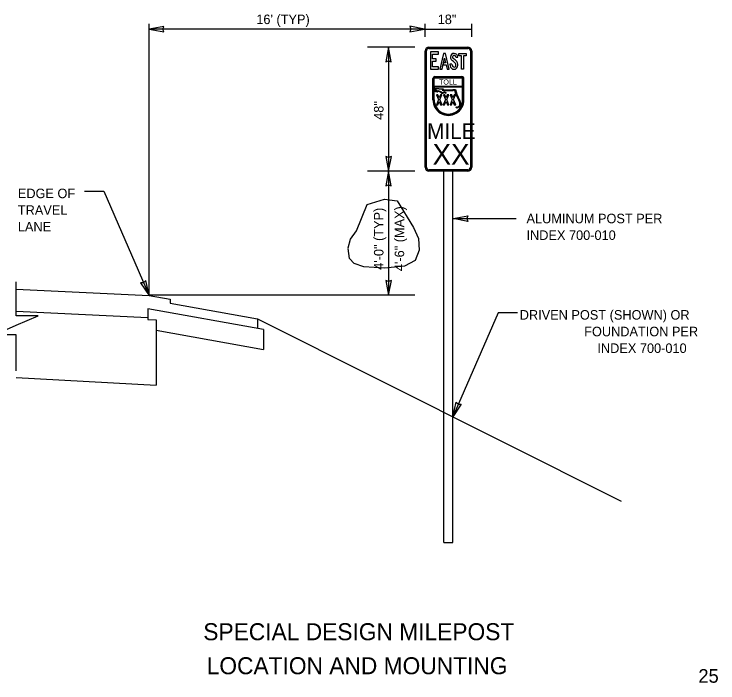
# Model space of a CAD drawing. Extents: x 56768 to 57406, y 11696 to 12105.
# Drawn here: x 57187.3 to 57394.2, y 11706.5 to 11903.1 of the extents above; entities that cross this region are included whole.
import ezdxf

# ---------------------------------------------------------------- set-up
doc = ezdxf.new("R2010")
doc.units = 0
for name, color, linetype in [('1', 7, 'Continuous'), ('52', 7, 'Continuous'), ('62', 7, 'Continuous'), ('Default', 7, 'Continuous'), ('DimLines_dp', 7, 'Continuous'), ('SignPanel', 7, 'Continuous'), ('TextMisc', 7, 'Continuous'), ('TextShtNo', 7, 'Continuous'), ('XSGrdLine_ex', 7, 'Continuous')]:
    doc.layers.add(name, color=color, linetype=linetype)

msp = doc.modelspace()

# ---------------------------------------------------------------- linework, layer by layer
at = {"layer": '1'}
for p, q in [((57313.6, 11786.05), (57313.6, 11856.93)), ((57316.26, 11784.71), (57316.26, 11856.93)), ((57313.6, 11747.72), (57313.6, 11786.05)), ((57316.26, 11747.72), (57316.26, 11784.71)), ((57313.6, 11747.72), (57316.26, 11747.72))]:
    msp.add_line(p, q, dxfattribs=at)
at = {"layer": '52'}
msp.add_line((57305.09, 11820.43), (57226.97, 11820.43), dxfattribs=at)
at = {"layer": '62'}
msp.add_lwpolyline([(57285.44, 11834.37), (57286.14, 11836.97), (57287.94, 11839.37), (57291.04, 11847.13), (57296.14, 11848.73), (57299.84, 11848.23), (57304.65, 11840.37), (57306.15, 11837.17), (57306.35, 11833.67), (57305.15, 11830.66), (57302.05, 11828.96), (57296.14, 11828.46), (57290.04, 11828.76), (57287.24, 11829.76), (57285.84, 11831.26), (57285.44, 11834.17)], dxfattribs=at)
at = {"layer": 'Default'}
msp.add_lwpolyline([(57187.88, 11798.24), (57187.88, 11808.8), (57181.42, 11808.8), (57187.88, 11811.61), (57194.34, 11814.43), (57187.88, 11814.43), (57187.88, 11824.43)], dxfattribs=at)
at = {"layer": 'DimLines_dp'}
for p, q in [((57226.97, 11820.43), (57226.97, 11900.25)), ((57231.32, 11899.52), (57226.97, 11898.71)), ((57230.99, 11898.71), (57231.32, 11899.52)), ((57307.91, 11898.71), (57303.56, 11899.55)), ((57303.56, 11899.55), (57303.89, 11898.71)), ((57308.09, 11896.42), (57308.09, 11900.25)), ((57321.78, 11896.42), (57321.78, 11900.25)), ((57308.09, 11898.71), (57226.97, 11898.71)), ((57226.97, 11898.71), (57231.32, 11897.87)), ((57231.32, 11897.87), (57230.99, 11898.71)), ((57303.89, 11898.71), (57303.56, 11897.9)), ((57303.56, 11897.9), (57307.91, 11898.71)), ((57308.09, 11898.71), (57321.78, 11898.71)), ((57305.09, 11893.42), (57291.17, 11893.42)), ((57297.35, 11893.42), (57296.51, 11889.07)), ((57297.35, 11893.42), (57297.35, 11856.93)), ((57298.16, 11889.07), (57297.35, 11893.42)), ((57296.51, 11889.07), (57297.35, 11889.4)), ((57297.35, 11889.4), (57298.16, 11889.07)), ((57297.35, 11860.95), (57296.54, 11861.28)), ((57296.54, 11861.28), (57297.35, 11856.93)), ((57297.35, 11860.95), (57296.54, 11861.28)), ((57296.54, 11861.28), (57297.35, 11856.93)), ((57297.35, 11856.93), (57298.19, 11861.28)), ((57298.19, 11861.28), (57297.35, 11860.95)), ((57297.35, 11856.93), (57298.19, 11861.28)), ((57298.19, 11861.28), (57297.35, 11860.95)), ((57305.09, 11856.93), (57291.17, 11856.93)), ((57297.35, 11856.93), (57296.51, 11852.58)), ((57297.35, 11856.93), (57297.35, 11820.43)), ((57298.16, 11852.58), (57297.35, 11856.93)), ((57296.51, 11852.58), (57297.35, 11852.91)), ((57297.35, 11852.91), (57298.16, 11852.58)), ((57208.01, 11851.04), (57213.65, 11851.04)), ((57213.65, 11851.04), (57226.97, 11820.42)), ((57316.32, 11842.98), (57320.67, 11843.82)), ((57320.67, 11843.82), (57320.34, 11842.98)), ((57316.32, 11842.98), (57334.84, 11842.98)), ((57320.67, 11842.17), (57316.32, 11842.98)), ((57320.34, 11842.98), (57320.67, 11842.17)), ((57225.37, 11824.11), (57224.49, 11824.09)), ((57224.49, 11824.09), (57226.97, 11820.42)), ((57226.01, 11824.75), (57225.37, 11824.11)), ((57226.97, 11820.42), (57226.01, 11824.75)), ((57297.35, 11824.45), (57296.54, 11824.78)), ((57296.54, 11824.78), (57297.35, 11820.43)), ((57297.35, 11820.43), (57298.19, 11824.78)), ((57298.19, 11824.78), (57297.35, 11824.45)), ((57329.59, 11815.33), (57316.26, 11784.71)), ((57335.23, 11815.33), (57329.59, 11815.33)), ((57316.26, 11784.71), (57317.23, 11789.03)), ((57318.74, 11788.38), (57316.26, 11784.71)), ((57317.23, 11789.03), (57317.87, 11788.4)), ((57317.87, 11788.4), (57318.74, 11788.38))]:
    msp.add_line(p, q, dxfattribs=at)
at = {"layer": 'SignPanel'}
for p, q in [((57317.13, 11890.42), (57317.71, 11890.42)), ((57317.13, 11890.42), (57317.71, 11890.42)), ((57317.13, 11890.42), (57317.71, 11890.42)), ((57315.99, 11888.38), (57315.4, 11888.38)), ((57315.99, 11888.38), (57315.4, 11888.38)), ((57315.99, 11888.38), (57315.4, 11888.38)), ((57310.37, 11877.91), (57310.37, 11884.19)), ((57310.57, 11877.91), (57310.57, 11884.19)), ((57310.75, 11881.91), (57310.75, 11884.19)), ((57310.94, 11884.76), (57318.93, 11884.76)), ((57310.94, 11884.56), (57318.93, 11884.56)), ((57310.94, 11884.37), (57318.93, 11884.37)), ((57319.12, 11881.91), (57319.12, 11884.19)), ((57319.31, 11877.91), (57319.31, 11884.19)), ((57319.5, 11877.91), (57319.5, 11884.19)), ((57310.75, 11881.91), (57319.12, 11881.91)), ((57310.75, 11877.91), (57310.75, 11881.71)), ((57310.75, 11881.71), (57319.12, 11881.71)), ((57311.14, 11880.26), (57310.97, 11881.35)), ((57310.97, 11881.35), (57313.35, 11881.16)), ((57313.19, 11880.95), (57311.24, 11881.1)), ((57311.24, 11881.1), (57311.34, 11880.46)), ((57312.23, 11881.01), (57312.23, 11881.01)), ((57313.32, 11880.59), (57313.19, 11880.95)), ((57313.35, 11881.16), (57313.48, 11880.82)), ((57313.48, 11880.82), (57316.21, 11880.82)), ((57316.21, 11880.82), (57316.31, 11880.97)), ((57316.31, 11880.97), (57317.05, 11880.97)), ((57317.05, 11880.97), (57317.38, 11879.54)), ((57319.12, 11877.91), (57319.12, 11881.71)), ((57311.59, 11880.2), (57311.14, 11880.26)), ((57311.34, 11880.46), (57311.53, 11880.44)), ((57311.53, 11880.44), (57311.8, 11880.65)), ((57311.84, 11880.4), (57311.59, 11880.2)), ((57311.8, 11880.65), (57312.71, 11880.36)), ((57312.6, 11880.15), (57311.84, 11880.4)), ((57313.13, 11879.65), (57312.6, 11880.15)), ((57312.71, 11880.36), (57313.17, 11879.94)), ((57313.77, 11880.03), (57313.13, 11879.65)), ((57313.17, 11879.94), (57313.78, 11880.3)), ((57316.33, 11880.59), (57313.32, 11880.59)), ((57314.15, 11879.77), (57313.77, 11880.03)), ((57313.78, 11880.3), (57314.27, 11879.96)), ((57314.27, 11879.96), (57314.15, 11879.77)), ((57316.44, 11880.74), (57316.33, 11880.59)), ((57316.87, 11880.74), (57316.44, 11880.74)), ((57317.17, 11879.45), (57316.87, 11880.74)), ((57317.6, 11878.75), (57317.17, 11879.45)), ((57317.38, 11879.54), (57317.83, 11878.81)), ((57317.6, 11878.57), (57317.6, 11878.75)), ((57317.83, 11878.81), (57317.83, 11878.63)), ((57318.03, 11877.86), (57317.6, 11878.57)), ((57317.83, 11878.63), (57318.24, 11877.96)), ((57318.27, 11877), (57318.03, 11877.86)), ((57318.24, 11877.96), (57318.5, 11877.03)), ((57318.27, 11876.28), (57318.27, 11877)), ((57318.5, 11877.03), (57318.5, 11876.17)), ((57317.16, 11875.63), (57317.29, 11875.82)), ((57317.39, 11875.47), (57317.16, 11875.63)), ((57317.29, 11875.82), (57317.43, 11875.72)), ((57317.74, 11875.56), (57317.39, 11875.47)), ((57317.43, 11875.72), (57317.64, 11875.77)), ((57317.64, 11875.77), (57318.27, 11876.28)), ((57318.5, 11876.17), (57317.74, 11875.56))]:
    msp.add_line(p, q, dxfattribs=at)
for points in [[(57309.23, 11893.42), (57320.64, 11893.42)], [(57308.09, 11858.07), (57308.09, 11892.28)], [(57308.47, 11858.07), (57308.47, 11892.28)], [(57309.23, 11893.04), (57320.64, 11893.04)], [(57321.4, 11892.28), (57321.4, 11858.07)], [(57321.78, 11892.28), (57321.78, 11858.07)], [(57320.64, 11857.31), (57309.23, 11857.31)], [(57320.64, 11856.93), (57309.23, 11856.93)]]:
    msp.add_lwpolyline(points, dxfattribs=at)
for points in [[(57310.29, 11887.65), (57310.29, 11889.27), (57311.31, 11889.27), (57311.31, 11889.98), (57310.29, 11889.98), (57310.29, 11891.3), (57312.02, 11891.3), (57312.02, 11892), (57309.64, 11892), (57309.64, 11886.94), (57312.02, 11886.94), (57312.02, 11887.65)], [(57310.29, 11887.65), (57310.29, 11889.27), (57311.31, 11889.27), (57311.31, 11889.98), (57310.29, 11889.98), (57310.29, 11891.3), (57312.02, 11891.3), (57312.02, 11892), (57309.64, 11892), (57309.64, 11886.94), (57312.02, 11886.94), (57312.02, 11887.65)], [(57310.29, 11887.65), (57310.29, 11889.27), (57311.31, 11889.27), (57311.31, 11889.98), (57310.29, 11889.98), (57310.29, 11891.3), (57312.02, 11891.3), (57312.02, 11892), (57309.64, 11892), (57309.64, 11886.94), (57312.02, 11886.94), (57312.02, 11887.65)], [(57314.26, 11888.17), (57314.54, 11886.94), (57315.14, 11886.94), (57314.12, 11891.52), (57313.49, 11891.52), (57312.47, 11886.94), (57313.08, 11886.94), (57313.35, 11888.17)], [(57313.49, 11888.81), (57313.35, 11888.17), (57314.26, 11888.17), (57314.54, 11886.94), (57315.14, 11886.94), (57314.12, 11891.52), (57313.49, 11891.52), (57312.47, 11886.94), (57313.08, 11886.94), (57313.81, 11890.21), (57314.12, 11888.81)], [(57313.49, 11888.81), (57313.35, 11888.17), (57314.26, 11888.17), (57314.54, 11886.94), (57315.14, 11886.94), (57314.12, 11891.52), (57313.49, 11891.52), (57312.47, 11886.94), (57313.08, 11886.94), (57313.81, 11890.21), (57314.12, 11888.81)], [(57318.77, 11890.88), (57318, 11890.88), (57318, 11891.52), (57320.14, 11891.52), (57320.14, 11890.88), (57319.36, 11890.88), (57319.36, 11886.94), (57318.77, 11886.94)], [(57318.77, 11890.88), (57318, 11890.88), (57318, 11891.52), (57320.14, 11891.52), (57320.14, 11890.88), (57319.36, 11890.88), (57319.36, 11886.94), (57318.77, 11886.94)], [(57318.77, 11890.88), (57318, 11890.88), (57318, 11891.52), (57320.14, 11891.52), (57320.14, 11890.88), (57319.36, 11890.88), (57319.36, 11886.94), (57318.77, 11886.94)], [(57313.81, 11890.21), (57314.12, 11888.81), (57313.49, 11888.81)], [(57311.83, 11876.49), (57312.23, 11877.47), (57312.64, 11876.49), (57313.07, 11876.49), (57312.45, 11877.98), (57313.02, 11879.34), (57312.59, 11879.34), (57312.23, 11878.49), (57311.88, 11879.34), (57311.45, 11879.34), (57312.02, 11877.98), (57311.4, 11876.49)], [(57313.84, 11876.49), (57314.25, 11877.47), (57314.66, 11876.49), (57315.08, 11876.49), (57314.46, 11877.98), (57315.03, 11879.34), (57314.61, 11879.34), (57314.25, 11878.49), (57313.89, 11879.34), (57313.46, 11879.34), (57314.04, 11877.98), (57313.41, 11876.49)], [(57315.86, 11876.49), (57316.27, 11877.47), (57316.67, 11876.49), (57317.1, 11876.49), (57316.48, 11877.98), (57317.05, 11879.34), (57316.62, 11879.34), (57316.27, 11878.49), (57315.91, 11879.34), (57315.48, 11879.34), (57316.05, 11877.98), (57315.43, 11876.49)]]:
    msp.add_lwpolyline(points, close=True, dxfattribs=at)
for centre, radius, start, end in [((57309.23, 11892.28), 1.14, 90, 180), ((57320.64, 11892.28), 1.14, 0, 90), ((57309.23, 11892.28), 0.76, 90, 180), ((57320.64, 11892.28), 0.76, 0, 90), ((57309.23, 11858.07), 1.14, 180, 270), ((57309.23, 11858.07), 0.76, 180, 270), ((57320.64, 11858.07), 1.14, 270, 360), ((57320.64, 11858.07), 0.76, 270, 360)]:
    msp.add_arc(centre, radius, start, end, dxfattribs=at)
for centre, major_axis, ratio, start_param, end_param in [((57316.62, 11890.39), (0, 1.19), 0.91923, 4.736267, 7.790596), ((57316.62, 11890.39), (0, 1.19), 0.91923, 4.736267, 7.790596), ((57316.62, 11890.39), (0, 1.19), 0.91923, 4.736267, 7.790596), ((57316.51, 11890.42), (0, 1.07), 0.91923, 1.534831, 2.511766), ((57316.51, 11890.42), (0, 1.07), 0.91923, 1.534831, 2.511766), ((57316.51, 11890.42), (0, 1.07), 0.91923, 1.534831, 2.511766), ((57313.91, 11885.49), (0, 4.63), 0.91923, 5.515137, 5.786988), ((57313.91, 11885.49), (0, 4.63), 0.91923, 5.515137, 5.786988), ((57313.91, 11885.49), (0, 4.63), 0.91923, 5.515137, 5.786988), ((57316.55, 11890.44), (0, 0.46), 0.91923, 0.87378, 2.656959), ((57316.55, 11890.44), (0, 0.46), 0.91923, 0.87378, 2.656959), ((57316.55, 11890.44), (0, 0.46), 0.91923, 0.87378, 2.656959), ((57316.62, 11890.37), (0, 0.558), 0.91923, 4.786904, 7.140738), ((57316.62, 11890.37), (0, 0.558), 0.91923, 4.786904, 7.140738), ((57316.62, 11890.37), (0, 0.558), 0.91923, 4.786904, 7.140738), ((57314.42, 11886.19), (0, 4.39), 0.91923, 5.462886, 5.782242), ((57314.42, 11886.19), (0, 4.39), 0.91923, 5.462886, 5.782242), ((57314.42, 11886.19), (0, 4.39), 0.91923, 5.462886, 5.782242), ((57316.44, 11888.19), (0, 1.42), 0.91923, 4.260987, 5.485755), ((57316.44, 11888.19), (0, 1.42), 0.91923, 4.260987, 5.485755), ((57316.44, 11888.19), (0, 1.42), 0.91923, 4.260987, 5.485755), ((57316.77, 11888.31), (0, 1.5), 0.91923, 1.526364, 2.701682), ((57316.77, 11888.31), (0, 1.5), 0.91923, 1.526364, 2.701682), ((57316.77, 11888.31), (0, 1.5), 0.91923, 1.526364, 2.701682), ((57316.83, 11888.33), (0, 0.911), 0.91923, 1.524757, 2.28214), ((57316.83, 11888.33), (0, 0.911), 0.91923, 1.524757, 2.28214), ((57316.83, 11888.33), (0, 0.911), 0.91923, 1.524757, 2.28214), ((57316.61, 11888.11), (0, 0.581), 0.91923, 2.261787, 4.23006), ((57316.61, 11888.11), (0, 0.581), 0.91923, 2.261787, 4.23006), ((57316.61, 11888.11), (0, 0.581), 0.91923, 2.261787, 4.23006), ((57316.58, 11888.12), (0, 1.24), 0.91923, 2.786047, 4.251692), ((57316.58, 11888.12), (0, 1.24), 0.91923, 2.786047, 4.251692), ((57316.58, 11888.12), (0, 1.24), 0.91923, 2.786047, 4.251692), ((57316.43, 11888.19), (0, 0.792), 0.91923, 4.254409, 5.632398), ((57316.43, 11888.19), (0, 0.792), 0.91923, 4.254409, 5.632398), ((57316.43, 11888.19), (0, 0.792), 0.91923, 4.254409, 5.632398), ((57310.95, 11884.18), (0, 0.57), 0.9997, 0, 1.570796), ((57310.95, 11884.18), (0, 0.38), 0.9997, 0, 1.570796), ((57310.95, 11884.18), (0, 0.19), 0.9997, 0, 1.570796), ((57318.93, 11884.18), (0, 0.57), 0.9997, 4.712389, 6.283185), ((57318.93, 11884.18), (0, 0.38), 0.9997, 4.712389, 6.283185), ((57318.93, 11884.18), (0, 0.19), 0.9997, 4.712389, 6.283185), ((57314.94, 11877.91), (0, -4.56), 0.9997, 4.712389, 7.853982), ((57314.94, 11877.91), (0, -4.37), 0.9997, 4.712389, 7.853982), ((57314.94, 11877.91), (0, -4.18), 0.9997, 4.712389, 7.853982)]:
    msp.add_ellipse(centre, major_axis=major_axis, ratio=ratio, start_param=start_param, end_param=end_param, dxfattribs=at)
at = {"layer": 'XSGrdLine_ex'}
for p, q in [((57226.97, 11820.42), (57233.13, 11819.31)), ((57233.13, 11819.31), (57233.13, 11818.14)), ((57233.13, 11818.14), (57258.85, 11813.51)), ((57226.56, 11816.48), (57226.56, 11813.33)), ((57260.55, 11810.37), (57226.56, 11816.48)), ((57226.56, 11813.33), (57229.03, 11813.18)), ((57229.03, 11813.18), (57229.03, 11794)), ((57258.85, 11813.51), (57258.85, 11810.67)), ((57229.03, 11810.22), (57260.55, 11804.55)), ((57260.55, 11810.37), (57260.55, 11804.55)), ((57187.88, 11796.28), (57229.03, 11794))]:
    msp.add_line(p, q, dxfattribs=at)
for points in [[(57187.88, 11822.28), (57226.97, 11820.42)], [(57187.88, 11815.78), (57226.56, 11813.95)], [(57258.85, 11813.51), (57365.73, 11759.9)]]:
    msp.add_lwpolyline(points, dxfattribs=at)

# ---------------------------------------------------------------- texts
at = {"layer": 'DimLines_dp'}
for s, p in [("16' (TYP)", (57258.48, 11900.18)), ('18"', (57311.8, 11900.18)), ('EDGE OF ', (57188.39, 11849)), ('TRAVEL ', (57188.39, 11844.1)), ('ALUMINUM POST PER', (57337.9, 11841.62)), ('LANE', (57188.39, 11839.2)), ('INDEX 700-010', (57337.9, 11836.72)), ('DRIVEN POST (SHOWN) OR', (57335.91, 11813.29)), ('FOUNDATION PER', (57354.85, 11808.39)), ('INDEX 700-010', (57358.74, 11803.49))]:
    msp.add_text(s, height=2.8, dxfattribs=at).set_placement(p)
for s, p in [('48"', (57295.86, 11872.03)), ('4\'-0" (TYP)', (57295.86, 11827.92)), ('4\'-6" (MAX)', (57301.94, 11827.53))]:
    msp.add_text(s, height=2.8, rotation=90, dxfattribs=at).set_placement(p)
at = {"layer": 'SignPanel'}
for s, height, p in [('TOLL', 1.519, (57312.18, 11882.38)), ('MILE', 4.562, (57308.68, 11866.42)), ('XX', 6.083, (57310.29, 11858.86))]:
    msp.add_text(s, height=height, dxfattribs=at).set_placement(p)
at = {"layer": 'TextMisc'}
for s, p in [('SPECIAL DESIGN MILEPOST ', (57242.9, 11719.02)), (' LOCATION AND MOUNTING  ', (57242.04, 11709.02))]:
    msp.add_text(s, height=5, rotation=360, dxfattribs=at).set_placement(p)
at = {"layer": 'TextShtNo'}
msp.add_text('25', height=4, rotation=360, dxfattribs=at).set_placement((57388.43, 11706.52))

doc.saveas('drawing.dxf')
